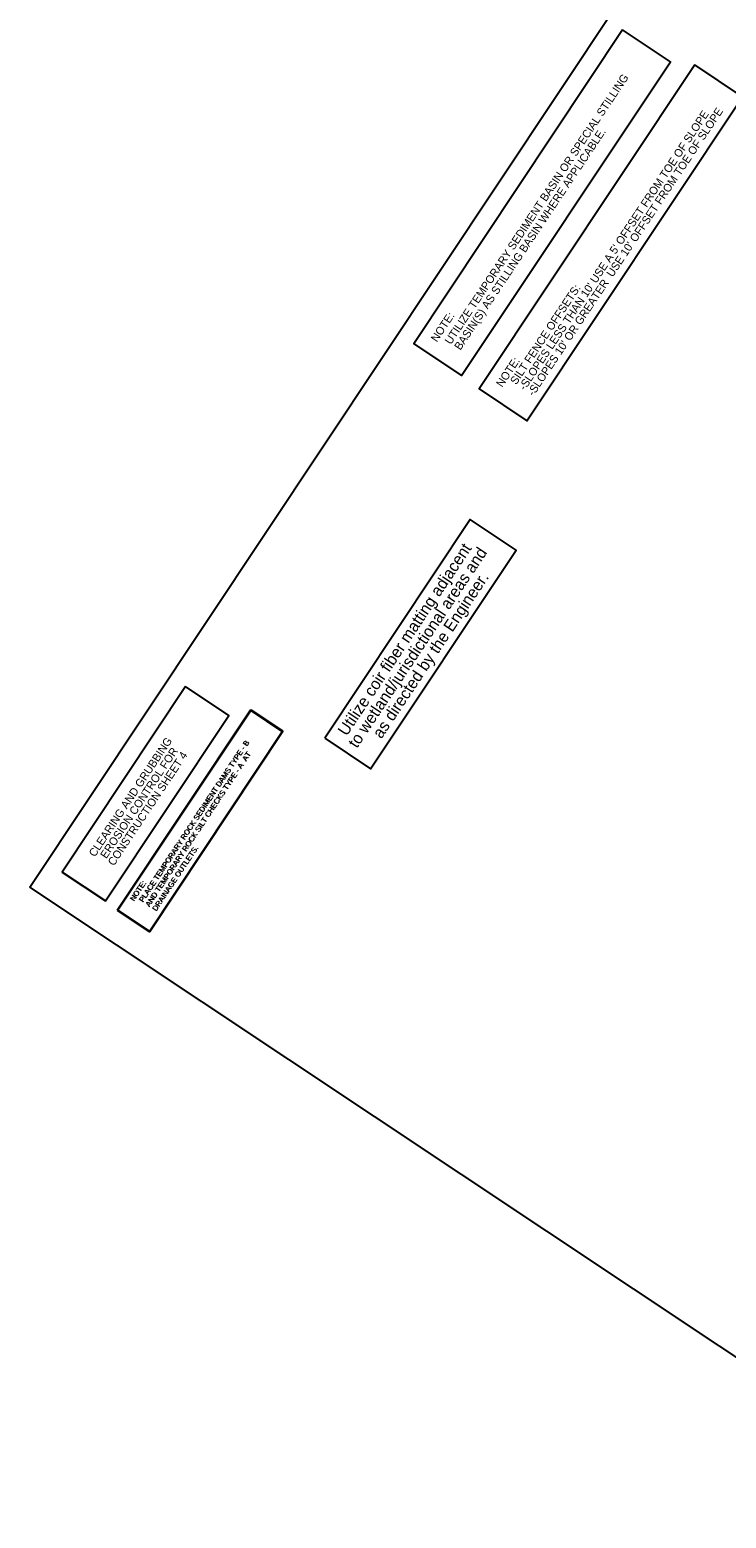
# Model space of a CAD drawing. Extents: x 2357856 to 2382083, y 331121 to 347536.
# Drawn here: x 2379358 to 2379985, y 331121 to 332460 of the extents above; entities that cross this region are included whole.
import ezdxf

# ---------------------------------------------------------------- set-up
doc = ezdxf.new("R2010")
doc.units = 0
for name, color, linetype in [('Cogo_Default_Point_CELL', 7, 'Continuous'), ('Default', 7, 'Continuous'), ('P_NCDOT_Horizontal_Alignment_Tick_Small', 7, 'Continuous'), ('P_RDY_North_Arrow_for_Plan_Sheets_CELL', 7, 'Continuous'), ('PSRM Summary Sheet CELL', 7, 'Continuous'), ('Scratch_Level_7', 7, 'Continuous'), ('Sheet_North_Arrow_CELL', 7, 'Continuous')]:
    doc.layers.add(name, color=color, linetype=linetype)

# ---------------------------------------------------------------- blocks, each defined once
blk = doc.blocks.new('CGNT2')
at = {"layer": 'Cogo_Default_Point_CELL'}
blk.add_lwpolyline([(-0.0901, 0.0144), (-0.0901, -0.0143), (0.0901, -0.0143), (0.0901, 0.0144)], close=True, dxfattribs=at)
for s, p in [('NOTE:', (-0.0778, 0.0077)), ('     PLACE TEMPORARY ROCK SEDIMENT DAMS TYPE - B', (-0.0824, 0.0016)), ('     AND TEMPORARY ROCK SILT CHECKS TYPE - A  AT', (-0.0826, -0.0042)), ('     DRAINAGE OUTLETS.', (-0.0825, -0.0103))]:
    blk.add_text(s, height=0.004, dxfattribs=at).set_placement(p)
blk = doc.blocks.new('SBNT')
at = {"layer": 'Scratch_Level_7'}
blk.add_lwpolyline([(0.09369, 0.01433), (-0.09477, 0.01433), (-0.09477, -0.01437), (0.09369, -0.01437)], close=True, dxfattribs=at)
for s, height, p in [('NOTE:  ', 0.004, (-0.08792, 0.005)), ('     UTILIZE TEMPORARY SEDIMENT BASIN OR SPECIAL STILLING', 0.0039998, (-0.09251, -0.00149)), ('     BASIN(S) AS STILLING BASIN WHERE APPLICABLE.', 0.004, (-0.09221, -0.007))]:
    blk.add_text(s, height=height, dxfattribs=at).set_placement(p)

msp = doc.modelspace()

# ---------------------------------------------------------------- linework, layer by layer
at = {"layer": 'Cogo_Default_Point_CELL'}
msp.add_lwpolyline([(2379436.8, 331667.3), (2379465.5, 331648.2), (2379585.3, 331828.3), (2379556.7, 331847.4)], close=True, dxfattribs=at)
at = {"layer": 'Default'}
msp.add_lwpolyline([(2379358.1, 331688.3), (2380202.9, 332957.9), (2380245.4, 332929.7), (2380969.1, 332259.1), (2380211.5, 331120.5)], close=True, dxfattribs=at)
at = {"layer": 'P_RDY_North_Arrow_for_Plan_Sheets_CELL'}
msp.add_lwpolyline([(2379498.1, 331868.7), (2379387.2, 331701.9), (2379426.2, 331676), (2379537.1, 331842.7)], close=True, dxfattribs=at)
at = {"layer": 'PSRM Summary Sheet CELL'}
msp.add_lwpolyline([(2379623.6, 331822.4), (2379664.8, 331794.9), (2379795.7, 331991.6), (2379754.4, 332019)], close=True, dxfattribs=at)
at = {"layer": 'Scratch_Level_7'}
msp.add_lwpolyline([(2379956.4, 332428.1), (2379762.4, 332136.6), (2379805.4, 332108), (2379999.4, 332399.5)], close=True, dxfattribs=at)

# ---------------------------------------------------------------- block references
at = {"layer": 'P_NCDOT_Horizontal_Alignment_Tick_Small', "xscale": 1199.9999999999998, "yscale": 1200.0000000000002, "rotation": 56.36098140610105}
msp.add_blockref('CGNT2', (2379511.7, 331748), dxfattribs=at)
at = {"layer": 'Sheet_North_Arrow_CELL', "xscale": 1800.0000000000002, "yscale": 1799.9999999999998, "rotation": 56.360981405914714}
msp.add_blockref('SBNT', (2379819.6, 332304.9), dxfattribs=at)

# ---------------------------------------------------------------- texts
at = {"layer": 'Cogo_Default_Point_CELL'}
for s, p in [('     PLACE TEMPORARY ROCK SEDIMENT DAMS TYPE - B', (2379454.7, 331666.5)), ('     AND TEMPORARY ROCK SILT CHECKS TYPE - A  AT', (2379460.4, 331662.4)), ('     DRAINAGE OUTLETS.', (2379466.6, 331658.5)), ('NOTE:', (2379451.7, 331675.1))]:
    msp.add_text(s, height=4.8, rotation=56.361, dxfattribs=at).set_placement(p)
at = {"layer": 'P_RDY_North_Arrow_for_Plan_Sheets_CELL'}
for s, p in [('CLEARING AND GRUBBING', (2379416.7, 331714.9)), ('EROSION CONTROL FOR', (2379427, 331713.4)), ('CONSTRUCTION SHEET 4', (2379433.8, 331706.9))]:
    msp.add_text(s, height=7.2, rotation=56.361, dxfattribs=at).set_placement(p)
at = {"layer": 'PSRM Summary Sheet CELL'}
for s, p in [('Utilize coir fiber matting adjacent', (2379643.3, 331823.6)), ('to wetland/jurisdictional areas and', (2379652.5, 331812.7)), ('as directed by the Engineer.', (2379674.5, 331821.2))]:
    msp.add_text(s, height=10.542, rotation=56.361, dxfattribs=at).set_placement(p)
at = {"layer": 'Scratch_Level_7'}
for s, p in [("-SLOPES 10' OR GREATER  USE 10' OFFSET FROM TOE OF SLOPE", (2379811.3, 332129.5)), ("-SLOPES LESS THAN 10' USE A 5' OFFSET FROM TOE OF SLOPE", (2379803.6, 332134.6)), ('SILT FENCE OFFSETS:', (2379795.8, 332139.8)), ('NOTE:  ', (2379783.2, 332137.5))]:
    msp.add_text(s, height=7.2, rotation=56.361, dxfattribs=at).set_placement(p)

doc.saveas('drawing.dxf')
